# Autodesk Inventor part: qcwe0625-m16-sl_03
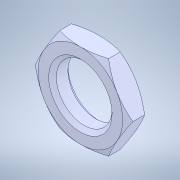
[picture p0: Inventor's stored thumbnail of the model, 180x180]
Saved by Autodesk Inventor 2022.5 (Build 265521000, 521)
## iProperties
Created: 2023-04
Part Number: qcwe0625-m16-sl_03
Material: Generic
Document SubType Name: Modeling
Designer: ImaoCorp
Density: 1 g/cm^3
Appearance: Default
Author: ImaoCorp
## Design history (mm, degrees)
feature "qcwe0625-m16-sl_03"
node "ソリッド1"
